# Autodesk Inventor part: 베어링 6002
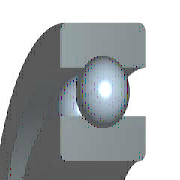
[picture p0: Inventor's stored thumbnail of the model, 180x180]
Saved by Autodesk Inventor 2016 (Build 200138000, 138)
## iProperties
IsCustomPart: 0
Created: 2015-10
Part Number: 베어링 6002
Material: 강, 연강
Description: 깊은 그루브 볼 베어링
Document SubType Name: Modeling
Standard: KS B 2023
Designer: mdu
Standards Organization: KS
Language: ko-KR
Size Designation: 6002 - 15 x 32 x 9
Categories: <MemberInstance><Categories><Category DisplayName="샤프트 부품" InternalName="7f7aeb1f-a693-4053-b835-cee3144e0d98" Mnemonic="SHFT"><Category DisplayName="베어링" Inter
Density: 1 g/cm^3
Appearance: 강철
Author: mdu
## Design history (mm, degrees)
sketch "스케치" dims "d0" = 4.42 (= -0.26 x WD + 0.26 x BD)
  geometry: L1 (2.29, 11.75)-(6.71, 11.75); L2 (4.5, 11.75)-(4.5, 9.54); L3 (4.5, 11.75)-(4.5, 13.96); L4 (2.858, 10.271)-(0, 10.271); L5 (0, 7.5)-(9, 7.5); L6 (2.858, 13.229)-(0, 13.229); L7 (0, 16)-(9, 16); L8 (9, 7.5)-(9, 10.271); L9 (6.142, 10.271)-(9, 10.271); L10 (6.142, 13.229)-(9, 13.229); L11 (9, 16)-(9, 13.229); L12 (-1.4, 0)-(8.4, 0) reference; L13 (0, -0.3)-(0, 5.3) reference
  constraints: 22 end point, 4 point on line, 2 collinear, 2 perpendicular, 2 symmetric about line, 1 midpoint, 1 parallel, 14 other
  dimensions: "d9" = 15 diameter of L5 L12 (= WD); "d11" = 32 diameter of L7 L12 (= BD); "d12" = 9 distance between parallel lines of L8 L13 (= KB); "d13" = 20.542 diameter of L9 L12 (= 0.326 x BD + 0.674 x WD)
revolve "본체" stored, may be unused: angle "d6" = 90 deg
revolve "볼" stored, may be unused: angle "d7" = 90 deg
pattern_circular "IDS_ARRAYBALL[SIMPL:T]" dims angle "d3" = 360 deg
body "Solid1"
fillet "모깎기1" dims "d1" = 0.3 (= KRS)
other parameters: "WD" = 15 [user parameter; used in 5 equation terms], "BD" = 32 [user parameter; used in 5 equation terms], "KB" = 9 [user parameter; used in 1 equation term], "KRS" = 0.3 [user parameter; used in 1 equation term], "d4" = 0, "d5" = 0, "d8" = 0, "d14" = 0, "d15" = 0, "BBA" = 0 [user parameter], "BC0" = 2850000 [user parameter], "BC" = 5590000 [user parameter], "BR" = 16 (= 0.5 x BD) [user parameter], "WR" = 7.5 (= 0.5 x WD) [user parameter]
